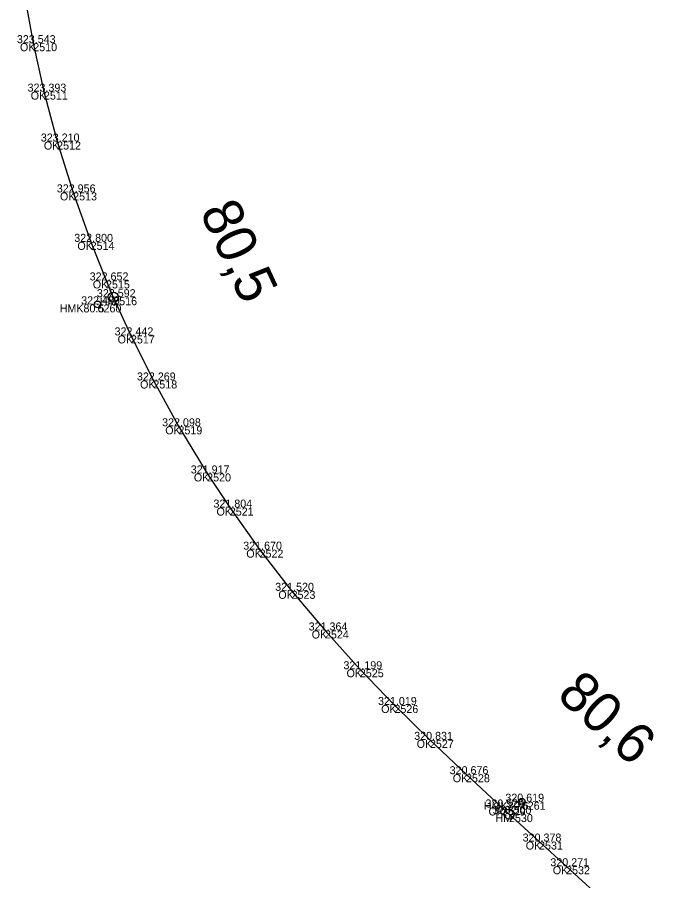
# Model space of a CAD drawing. Extents: x -621782 to -610392, y -1141853 to -1122321.
# Drawn here: x -614230.9 to -614135.2, y -1130582.8 to -1130453.4 of the extents above; entities that cross this region are included whole.
import ezdxf

# ---------------------------------------------------------------- set-up
doc = ezdxf.new("R2010")
doc.units = 0
for name, color, linetype in [('Vrstva 1', 7, 'Continuous'), ('Vrstva 60', 7, 'Continuous'), ('Vrstva 61', 7, 'Continuous'), ('Vrstva 62', 7, 'Continuous'), ('Vrstva 7', 7, 'Continuous')]:
    doc.layers.add(name, color=color, linetype=linetype)

msp = doc.modelspace()

# ---------------------------------------------------------------- linework, layer by layer
at = {"layer": 'Vrstva 1'}
msp.add_lwpolyline([(-614229.85, -1130449.52), (-614228.46, -1130457.28), (-614226.86, -1130464.54), (-614224.88, -1130472.02), (-614222.48, -1130479.64), (-614219.86, -1130487.05), (-614217.56, -1130492.83), (-614216.48, -1130495.34), (-614213.83, -1130501.07), (-614210.47, -1130507.82), (-614206.71, -1130514.69), (-614202.41, -1130521.75), (-614199.02, -1130526.87), (-614194.56, -1130533.17), (-614189.77, -1130539.34), (-614184.76, -1130545.28), (-614179.54, -1130551.09), (-614174.36, -1130556.45), (-614169.04, -1130561.67), (-614163.64, -1130566.82), (-614158.28, -1130571.8), (-614157.2, -1130572.79), (-614152.7, -1130576.91), (-614148.65, -1130580.61), (-614143.92, -1130584.95)], dxfattribs=at)
at = {"layer": 'Vrstva 60'}
for p, q in [((-614228.46, -1130457.28), (-614228.46, -1130457.28)), ((-614226.86, -1130464.54), (-614226.86, -1130464.54)), ((-614224.88, -1130472.02), (-614224.88, -1130472.02)), ((-614222.48, -1130479.64), (-614222.48, -1130479.64)), ((-614219.86, -1130487.05), (-614219.86, -1130487.05)), ((-614217.56, -1130492.83), (-614217.56, -1130492.83)), ((-614216.48, -1130495.34), (-614216.48, -1130495.34)), ((-614218.83, -1130496.42), (-614218.83, -1130496.42)), ((-614213.83, -1130501.07), (-614213.83, -1130501.07)), ((-614210.47, -1130507.82), (-614210.47, -1130507.82)), ((-614206.71, -1130514.69), (-614206.71, -1130514.69)), ((-614202.41, -1130521.75), (-614202.41, -1130521.75)), ((-614199.02, -1130526.87), (-614199.02, -1130526.87)), ((-614194.56, -1130533.17), (-614194.56, -1130533.17)), ((-614189.77, -1130539.34), (-614189.77, -1130539.34)), ((-614184.76, -1130545.28), (-614184.76, -1130545.28)), ((-614179.54, -1130551.09), (-614179.54, -1130551.09)), ((-614174.36, -1130556.45), (-614174.36, -1130556.45)), ((-614169.04, -1130561.67), (-614169.04, -1130561.67)), ((-614163.64, -1130566.82), (-614163.64, -1130566.82)), ((-614155.29, -1130570.94), (-614155.29, -1130570.94)), ((-614158.28, -1130571.8), (-614158.28, -1130571.8)), ((-614157.2, -1130572.79), (-614157.2, -1130572.79)), ((-614152.7, -1130576.91), (-614152.7, -1130576.91)), ((-614148.65, -1130580.61), (-614148.65, -1130580.61))]:
    msp.add_line(p, q, dxfattribs=at)
at = {"layer": 'Vrstva 7'}
for p, q in [((-614218.85, -1130496.37), (-614218.81, -1130496.47)), ((-614155.33, -1130570.91), (-614155.26, -1130570.98))]:
    msp.add_line(p, q, dxfattribs=at)
for centre, radius in [((-614216.48, -1130495.34), 0.75), ((-614218.83, -1130496.42), 0.5), ((-614155.29, -1130570.94), 0.5), ((-614157.2, -1130572.79), 0.75)]:
    msp.add_circle(centre, radius, dxfattribs=at)

# ---------------------------------------------------------------- texts
at = {"layer": 'Vrstva 60'}
for s, p in [('2510', (-614228.46, -1130458.48)), ('2511', (-614226.86, -1130465.74)), ('2512', (-614224.88, -1130473.22)), ('2513', (-614222.48, -1130480.84)), ('2514', (-614219.86, -1130488.25)), ('2515', (-614217.56, -1130494.03)), ('2516', (-614216.48, -1130496.54)), ('6260', (-614218.83, -1130497.62)), ('2517', (-614213.83, -1130502.27)), ('2518', (-614210.47, -1130509.02)), ('2519', (-614206.71, -1130515.89)), ('2520', (-614202.41, -1130522.95)), ('2521', (-614199.02, -1130528.07)), ('2522', (-614194.56, -1130534.37)), ('2523', (-614189.77, -1130540.54)), ('2524', (-614184.76, -1130546.48)), ('2525', (-614179.54, -1130552.29)), ('2526', (-614174.36, -1130557.65)), ('2527', (-614169.04, -1130562.87)), ('2528', (-614163.64, -1130568.02)), ('6261', (-614155.29, -1130572.14)), ('2529', (-614158.28, -1130573)), ('2530', (-614157.2, -1130573.99)), ('2531', (-614152.7, -1130578.11)), ('2532', (-614148.65, -1130581.81))]:
    msp.add_text(s, height=1.2, dxfattribs=at).set_placement(p)
at = {"layer": 'Vrstva 61'}
for s, p in [('323.543', (-614230.91, -1130457.28)), ('323.393', (-614229.31, -1130464.54)), ('323.210', (-614227.33, -1130472.02)), ('322.956', (-614224.93, -1130479.64)), ('322.800', (-614222.32, -1130487.05)), ('322.652', (-614220.01, -1130492.83)), ('322.592', (-614218.93, -1130495.34)), ('322.489', (-614221.28, -1130496.42)), ('322.442', (-614216.28, -1130501.07)), ('322.269', (-614212.93, -1130507.82)), ('322.098', (-614209.16, -1130514.69)), ('321.917', (-614204.87, -1130521.75)), ('321.804', (-614201.47, -1130526.87)), ('321.670', (-614197.01, -1130533.17)), ('321.520', (-614192.22, -1130539.34)), ('321.364', (-614187.21, -1130545.28)), ('321.199', (-614182, -1130551.09)), ('321.019', (-614176.82, -1130556.45)), ('320.831', (-614171.4, -1130561.67)), ('320.676', (-614166.09, -1130566.82)), ('320.619', (-614157.75, -1130570.94)), ('320.528', (-614160.73, -1130571.8)), ('320.500', (-614159.65, -1130572.79)), ('320.378', (-614155.16, -1130576.91)), ('320.271', (-614151.01, -1130580.61))]:
    msp.add_text(s, height=1.2, dxfattribs=at).set_placement(p)
at = {"layer": 'Vrstva 62'}
for s, p in [('OK', (-614230.45, -1130458.48)), ('OK', (-614228.84, -1130465.74)), ('OK', (-614226.87, -1130473.22)), ('OK', (-614224.46, -1130480.84)), ('OK', (-614221.85, -1130488.25)), ('OK', (-614219.54, -1130494.03)), ('HM', (-614218.51, -1130496.54)), ('HMK80.5', (-614224.5, -1130497.62)), ('OK', (-614215.82, -1130502.27)), ('OK', (-614212.46, -1130509.02)), ('OK', (-614208.69, -1130515.89)), ('OK', (-614204.4, -1130522.95)), ('OK', (-614201.01, -1130528.07)), ('OK', (-614196.55, -1130534.37)), ('OK', (-614191.75, -1130540.54)), ('OK', (-614186.75, -1130546.48)), ('OK', (-614181.53, -1130552.29)), ('OK', (-614176.35, -1130557.65)), ('OK', (-614171.03, -1130562.87)), ('OK', (-614165.62, -1130568.02)), ('HMK80.6', (-614160.96, -1130572.14)), ('OK', (-614160.26, -1130573)), ('HM', (-614159.23, -1130573.99)), ('OK', (-614154.69, -1130578.11)), ('OK', (-614150.64, -1130581.81))]:
    msp.add_text(s, height=1.2, dxfattribs=at).set_placement(p)
at = {"layer": 'Vrstva 7'}
for s, rotation, p in [('80,5', 294.7707, (-614203.58, -1130482.51)), ('80,6', 317.4872, (-614150.24, -1130555.23))]:
    msp.add_text(s, height=6, rotation=rotation, dxfattribs=at).set_placement(p)

doc.saveas('drawing.dxf')
